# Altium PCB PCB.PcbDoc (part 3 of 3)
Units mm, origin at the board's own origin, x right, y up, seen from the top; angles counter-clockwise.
Board outline 43.18 x 22.86 mm, 6 copper layers (TOP, L2_GND, L3_SIG, L4_PWR, L5_GND, BOTTOM), stack 1.573 mm thick; 127 components, 116 nets, 532 pads, 386 vias.
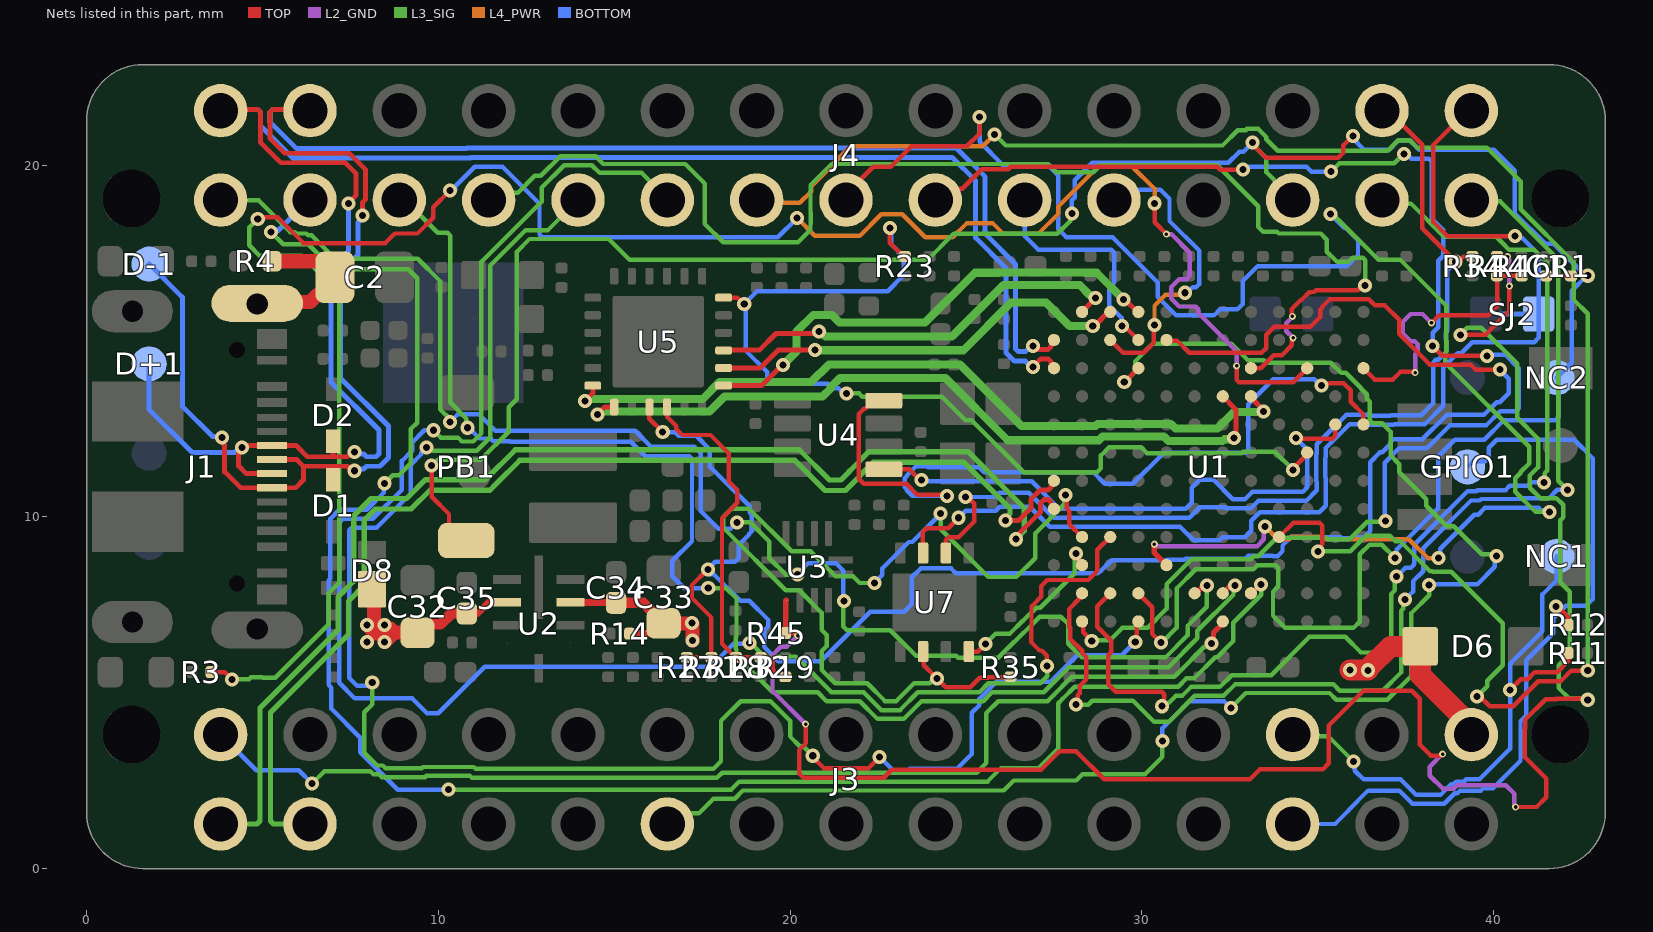
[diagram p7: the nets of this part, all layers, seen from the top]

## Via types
v1: diameter 0.4, hole 0.2, TOP to BOTTOM, tented both sides, 318 vias
v2: diameter 0.2, hole 0.1, TOP to L2_GND, tented both sides, 68 vias

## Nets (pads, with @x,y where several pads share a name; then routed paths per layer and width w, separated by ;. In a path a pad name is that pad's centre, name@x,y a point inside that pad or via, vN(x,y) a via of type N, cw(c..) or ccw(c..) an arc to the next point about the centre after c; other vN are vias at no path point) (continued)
NetR44_1: R44.1 R45.1 U3.1 | length 54.8
  TOP w0.127: v2(20.442,4.108) 20.442,3.56 20.255,3.373 20.255,2.71 20.382,2.582 22.664,2.582 22.895,2.813 27.134,2.813 27.66,3.34 28.13,3.34 28.93,2.54 33.075,2.54 33.356,2.821 35.145,2.821 35.318,2.994 35.318,4.07 36.303,5.056 37.673,5.056 37.9,4.828 37.9,3.531 38.215,3.215 38.508,3.215 v2(38.551,3.259) ; v1(39.056,15.178) 39.772,15.178 40.453,15.859 v2(40.453,16.565) ; R44.1@40.1,17.406 40.367,17.406 40.373,17.399 v2(40.403,17.399) ; v2(40.628,1.753) 41.223,1.753 41.5,2.031 41.5,2.562 40.894,3.168 40.894,3.969 40.905,3.98 40.905,4.243 41.482,4.82 41.768,4.82 41.774,4.826 42.656,4.826 v1(42.68,4.802)
  TOP w0.15: U3.1@19.889,7.63 19.875,7.616 R45.1@19.875,6.7 20.139,6.7 v2(20.214,6.625)
  L2_GND w0.127: v2(20.214,6.625) 19.899,6.31 19.737,6.31 19.5,6.073 19.5,5.05 v2(20.442,4.108) ; v2(38.551,3.259) 38.186,2.894 38.186,2.644 38.553,2.277 38.871,2.277 38.963,2.37 40.351,2.37 40.594,2.127 40.594,1.787 v2(40.628,1.753) ; v2(40.403,17.399) 40.403,17.379 40.45,17.332 40.45,16.568 v2(40.453,16.565)
  L3_SIG w0.127: v1(39.056,15.178) 39.257,15.379 39.655,15.379 40.673,14.362 40.673,12.82 41.268,12.225 41.268,11.415 41.032,11.179 41.032,10.834 41.334,10.533 41.79,10.533 41.979,10.343 41.979,9.985 41.899,9.905 41.899,8.142 42.172,7.869 42.172,6.106 41.849,5.783 41.849,5.139 42.159,4.828 42.654,4.828 v1(42.68,4.802)
NetU1_E11: U1.E11 U4.1 | length 16.4
  TOP w0.127: U4.1@22.765,11.356 23.388,11.356 23.691,11.053 v1(23.74,11.053) ; v1(34.379,12.246) 34.395,12.23 35.428,12.23 35.502,12.304 U1.E11@35.502,12.63
  BOTTOM w0.127: v1(23.74,11.053) 23.781,11.012 26.869,11.012 27.648,10.233 31.249,10.233 31.42,10.404 31.42,10.833 31.642,11.056 32.037,11.056 32.589,10.503 32.933,10.503 33.14,10.71 34.573,10.71 34.705,10.842 34.705,11.92 v1(34.379,12.246)
NetU1_E12: U1.E12 U4.4 | length 23.3
  TOP w0.127: U4.4@22.665,13.306 22.365,13.306 22.13,13.071 22.094,13.071 21.949,12.927 21.949,11.085 22.094,10.94 23.301,10.94 23.616,10.625 24.431,10.625 v1(24.462,10.594) ; v1(35.104,13.742) 35.155,13.794 35.35,13.794 35.351,13.796 35.745,13.796 35.937,13.603 35.937,13.279 36.302,12.913 U1.E12@36.302,12.63
  BOTTOM w0.127: v1@24.456,10.6 23.477,10.6 23.314,10.763 23.314,10.8 23.266,10.847 23.266,11.107 23.314,11.155 23.314,11.179 23.578,11.443 23.902,11.443 23.927,11.419 25.364,11.419 25.516,11.266 28.627,11.266 28.95,10.943 29.746,10.943 30.636,11.833 32.466,11.833 32.476,11.823 32.956,11.823 33.03,11.898 33.03,13.205 33.739,13.913 34.902,13.913 35.073,13.742 v1(35.104,13.742)
NetU1_K2: U1.K2 U7.4 | length 4.9
  TOP w0.127: U7.4@25.082,6.171 25.332,6.171 v1(25.553,6.391)
  TOP w0.15: v1(28.125,8.96) 28.173,8.913 28.173,8.814 28.302,8.684 U1.K2@28.302,8.63
  L3_SIG w0.127: v1(25.553,6.391) 25.845,6.684 26.25,6.684 26.613,7.047 26.623,7.047 26.996,7.42 27.115,7.42 28.091,8.396 28.091,8.927 v1(28.125,8.96)
PA20_TCC4_WO0_1: J4.16 U1.K5 | length 48
  TOP w0.127: J4.16@21.59,19.05 21.59,19.179 22.365,19.954 22.868,19.954 23.451,20.538 25.027,20.538 25.39,20.9 v1(25.39,21.37)
  TOP w0.15: v2(30.357,9.224) 30.357,8.975 U1.K5@30.702,8.63
  L2_GND w0.127: v2(30.357,9.224) 30.377,9.224 30.431,9.17 33.279,9.17 33.471,9.362 33.471,9.701 v1(33.502,9.733)
  L3_SIG w0.127: v1(35.368,18.608) 35.433,18.608 36.734,17.307 37.353,17.307 38.661,15.999 38.661,14.695 38.621,14.655 38.621,14.387 41.014,11.995 41.014,11.52 40.778,11.284 40.778,11.26 40.616,11.098 40.616,10.72 41.194,10.142 v1(41.589,10.142)
  L4_PWR w0.127: v1(33.502,9.733) 33.866,9.37 34.192,9.37 34.255,9.433 35.157,9.433 35.22,9.37 37.59,9.37 38.129,8.83 v1(38.432,8.83)
  BOTTOM w0.127: v1(25.39,21.37) 25.39,20.666 26.053,20.002 27.334,20.002 27.626,19.71 27.626,18.794 27.622,18.79 27.622,18.186 27.851,17.957 27.978,17.957 27.979,17.956 29.169,17.956 30.449,16.677 30.449,16.265 30.984,15.73 32.051,15.73 32.223,15.902 32.72,15.902 32.866,16.047 32.866,16.706 33.291,17.131 35.828,17.131 36.148,17.451 36.148,17.717 36.15,17.72 36.15,17.87 35.799,18.221 35.755,18.221 v1(35.368,18.608) ; v1(38.432,8.83) 38.485,8.883 38.485,9.094 39.456,10.065 39.563,10.065 39.754,10.256 40.656,10.256 ; 40.656,10.255 41.282,10.255 41.343,10.194 41.537,10.194 v1(41.589,10.142)
PA21_TCC4_WO1_1: J4.18 U1.M2 | length 41.3
  TOP w0.127: J4.18@24.13,19.05 24.205,19.125 24.622,19.125 24.829,19.332 24.899,19.332 25.451,19.884 26.2,19.884 26.276,19.961 32.144,19.961 32.228,19.876 v1(32.876,19.876) ; U1.M2@28.302,7.03 28.337,6.996 28.337,6.718 v1(28.577,6.477) ; v1(38.271,14.857) 38.545,14.583 39.455,14.583 39.459,14.579 v1(39.813,14.579)
  L3_SIG w0.127: v1(28.577,6.477) 28.59,6.49 29.085,6.49 29.449,6.854 30.169,6.854 30.705,7.39 30.705,8.086 31.414,8.795 33.099,8.795 33.183,8.879 33.309,8.879 33.839,9.409 34.231,9.409 34.236,9.415 35.23,9.415 35.277,9.367 35.913,9.367 36.41,9.864 36.908,9.864 v1(36.931,9.888) ; v1(35.378,19.819) 35.619,20.06 37.182,20.06 37.439,20.317 v1(37.456,20.317)
  BOTTOM w0.127: v1(32.876,19.876) 32.95,19.876 33.035,19.961 34.684,19.961 34.826,19.819 v1(35.378,19.819) ; v1(36.931,9.888) 36.908,9.912 36.908,11.545 37.316,11.953 38.08,11.953 38.095,11.969 38.122,11.969 38.767,12.614 39.799,12.614 40.194,13.009 40.64,13.009 40.717,13.086 40.717,14.227 40.326,14.618 39.852,14.618 v1(39.813,14.579) ; v1(37.456,20.317) 37.53,20.317 37.662,20.185 38.159,20.185 38.238,20.106 38.238,18.495 38.574,18.16 38.574,17.428 38.428,17.282 38.428,15.395 38.271,15.238 v1(38.271,14.857)
PA23_TCC5_WO1_1: J4.10 U1.M4 | length 48.9
  TOP w0.127: v1(20.645,3.211) 20.645,3.171 20.956,2.859 22.236,2.859 22.548,3.172 v1(22.548,3.175) ; v1(29.814,6.448) 29.86,6.493 29.86,6.987 U1.M4@29.902,7.03
  L3_SIG w0.127: v1(8.12,5.294) 8.12,4.67 7.896,4.445 7.896,3.297 8.259,2.934 8.422,2.934 8.496,2.859 9.525,2.859 9.556,2.891 11.005,2.891 11.061,2.835 17.816,2.835 18.036,3.055 18.036,4.202 18.594,4.761 19.444,4.761 20.001,4.204 20.001,3.759 20.276,3.484 20.372,3.484 v1(20.645,3.211) ; v1(9.667,11.976) 9.741,11.976 9.832,11.885 11.094,11.885 11.478,12.269 11.478,17.147 12.488,18.157 13.117,18.157 J4.10@13.97,19.01
  BOTTOM w0.127: v1(8.12,5.294) 8.028,5.202 7.688,5.202 7.46,5.429 7.46,9.62 7.535,9.694 8.243,9.694 9.218,10.669 9.218,11.487 9.507,11.777 9.507,11.823 9.661,11.976 v1(9.667,11.976) ; v1(22.548,3.175) 22.984,2.738 23.307,2.738 23.406,2.836 24.743,2.836 25.165,3.259 25.165,4.433 25.383,4.651 25.383,4.835 25.862,5.315 27.414,5.315 28.165,6.066 29.432,6.066 v1(29.814,6.448)
PB11_TCC3_WO6_1: J4.14 U1.J9 | length 53.3
  TOP w0.127: U1.J9@33.902,9.43 34.303,9.831 35.059,9.831 35.137,9.753 35.137,9.219 35.015,9.097 v1(35.015,9.023) ; v1(39.534,4.897) 39.608,4.897 39.89,4.615 40.558,4.615 41.271,5.328 41.557,5.328 41.563,5.334 41.917,5.334 41.962,5.378 41.962,5.38 42.19,5.609 42.192,5.609 42.215,5.631 v1(42.68,5.631)
  L3_SIG w0.127: v1(25.817,20.876) 26.132,20.561 32.295,20.561 32.731,20.997 32.952,20.997 32.986,21.032 33.309,21.032 33.538,20.803 33.538,20.741 33.869,20.41 36.997,20.41 37.295,20.707 37.618,20.707 37.823,20.503 39.805,20.503 40.426,19.882 40.43,19.882 40.774,19.538 40.774,18.749 42.275,17.248 42.275,16.184 42.68,15.78 v1(42.68,5.631) ; v1(35.015,9.023) 35.928,9.023 36.371,9.466 37.055,9.466 37.206,9.315 37.34,9.315 38.205,8.45 38.261,8.45 38.271,8.44 38.799,8.44 40.262,6.977 40.262,5.781 40.205,5.724 40.203,5.724 39.826,5.346 39.826,5.188 v1(39.534,4.897)
  L4_PWR w0.127: J4.14@19.05,19.05 19.169,18.931 20.276,18.931 20.598,19.253 20.598,19.405 21.729,20.536 25.476,20.536 v1(25.817,20.876)
PB16_GPIO_1: R3.2 U1.C10 | length 57.9
  TOP w0.127: R3.2@3.536,5.59 3.927,5.59 v1(4.134,5.384) ; v1(4.865,18.476) 4.906,18.517 5.435,18.517 6.164,17.788 8.488,17.788 8.76,18.06 9.405,18.06 9.852,18.506 9.852,18.802 v1(10.333,19.283) ; v1(30.365,18.918) 30.365,18.377 v2(30.7,18.042) ; v2@32.699,14.298 v2(32.699,14.294) 32.695,14.289 32.695,13.901 32.764,13.832 34.305,13.832 U1.C10@34.702,14.23
  L2_GND w0.127: v2(30.7,18.042) 30.717,18.042 30.719,18.043 30.837,18.043 31.366,17.515 31.366,16.852 31.278,16.765 31.066,16.765 30.837,16.536 30.837,16.213 31.066,15.984 31.529,15.984 31.603,15.909 31.603,15.799 32.699,14.703 v2(32.699,14.294)
  L3_SIG w0.127: v1(4.134,5.384) 4.616,5.384 4.67,5.437 4.994,5.437 5.001,5.431 5.364,5.431 6.882,6.948 6.882,7.837 7.178,8.134 7.178,16.372 6.121,17.429 4.912,17.429 4.62,17.722 4.62,18.231 v1(4.865,18.476)
  L4_PWR w0.127: v1(20.2,18.5) 20.702,17.998 21.985,17.998 22.594,18.607 23.189,18.607 23.845,17.951 24.623,17.951 25.018,18.346 25.769,18.346 26.055,18.06 27.064,18.06 27.621,18.616 27.621,18.653 27.623,18.655 27.623,18.828 28.797,20.002 29.689,20.002 30.365,19.326 v1(30.365,18.918)
  BOTTOM w0.127: v1(10.333,19.283) 10.479,19.283 10.479,19.404 11.036,19.961 11.824,19.961 12.875,18.909 12.875,18.025 12.95,17.951 19.651,17.951 v1(20.2,18.5)
PB24_TCC6_WO1_1: J4.8 U1.C8 | length 36.4
  TOP w0.127: U1.C8@33.102,14.23 33.386,14.23 33.751,14.596 33.985,14.596 34.268,14.879 34.268,15.008 34.286,15.026 34.286,15.077 v2(34.3,15.091) ; v2(34.283,15.701) 34.269,15.715 34.269,15.766 34.268,15.767 34.268,15.912 34.499,16.143 34.505,16.143 34.558,16.195 34.567,16.195 34.758,16.386 34.802,16.386 34.812,16.396 34.9,16.396 34.953,16.45 36.144,16.45 36.28,16.586 v1(36.35,16.586)
  L2_GND w0.127: v2(34.283,15.701) 34.283,15.685 34.11,15.513 34.11,15.28 v2(34.3,15.091)
  L3_SIG w0.127: J4.8@11.43,19.05 11.592,19.212 12.255,19.212 12.744,19.7 12.914,19.7 13.47,20.256 14.47,20.256 14.691,20.035 17.018,20.035 17.574,19.479 17.574,18.331 18.097,17.808 20.226,17.808 20.58,18.163 20.58,18.328 20.59,18.338 20.59,18.662 20.58,18.672 20.58,19.437 21.178,20.035 27.344,20.035 27.574,19.804 28.617,19.804 28.815,20.002 32.145,20.002 33.312,18.835 33.312,18.247 33.447,18.112 33.844,18.112 33.896,18.06 35.087,18.06 35.262,17.884 35.262,17.544 35.555,17.251 35.879,17.251 35.999,17.371 36.28,17.371 36.354,17.297 36.354,16.59 v1(36.35,16.586)
PC02_GPIO_1: R44.2 R46.1 U1.C12 | length 8.1
  TOP w0.127: U1.C12@36.302,14.23 36.626,13.906 37.137,13.906 37.353,14.123 37.752,14.123 v2(37.77,14.105) ; v2(38.237,15.515) 38.453,15.731 39.847,15.731 40.1,15.984 R44.2@40.1,16.856 R46.1@40.8,16.856
  L2_GND w0.127: v2(37.77,14.105) 37.77,14.633 37.84,14.703 37.84,14.915 37.765,14.99 37.649,14.99 37.421,15.218 37.421,15.542 37.649,15.771 37.982,15.771 v2(38.237,15.515)
PC19_TCC1_WO4_1: J4.22 U1.B3 | length 8.7
  TOP w0.127: U1.B3@29.102,15.03 29.468,14.664 30.054,14.664 30.337,14.948 30.337,15.437 v1(30.362,15.461)
  L4_PWR w0.127: v1(30.362,15.461) 30.362,16.006 30.673,16.318 31.036,16.318 31.04,16.322 31.175,16.322 v1(31.227,16.374)
  BOTTOM w0.127: J4.22@29.21,19.05 29.469,19.309 30.527,19.309 30.788,19.047 30.788,18.416 31.63,17.573 31.63,16.621 31.54,16.532 31.443,16.532 31.285,16.374 v1(31.227,16.374)
PC20_TCC1_WO5_1: J4.20 U1.B4 | length 6.7
  TOP w0.127: v1(29.432,15.432) 29.501,15.432 U1.B4@29.902,15.03
  BOTTOM w0.127: J4.20@26.67,19.05 26.67,17.986 27.054,17.602 29.128,17.602 29.213,17.516 29.213,16.674 29.076,16.537 29.076,16.015 29.432,15.659 v1(29.432,15.432)
PD11_TCC2_WO2_1: J4.12 U1.J3 | length 50.8
  TOP w0.127: v1(27.308,5.761) 27.303,5.766 27.303,6.054 27.154,6.203 27.091,6.203 26.862,6.431 26.862,6.495 26.862,6.755 26.864,6.757 26.864,7.455 27.137,7.727 27.137,8.031 27.314,8.208 28.481,8.208 28.737,8.464 28.737,9.065 U1.J3@29.102,9.43
  L3_SIG w0.127: v1(9.864,12.465) 10.072,12.257 10.558,12.257 10.67,12.146 10.996,12.146 11.224,12.374 11.224,17.252 12.94,18.968 12.94,19.367 13.575,20.002 14.365,20.002 14.586,19.781 15.779,19.781 J4.12@16.51,19.05 ; v1(18.846,6.417) 18.885,6.417 19.269,6.033 20.157,6.033 21.175,5.015 22.089,5.015 22.593,4.51 23.127,4.51 23.631,5.015 25.384,5.015 25.638,5.269 27.109,5.269 27.308,5.467 v1(27.308,5.761)
  BOTTOM w0.127: v1(9.864,12.465) 9.86,12.462 9.6,12.462 9.253,12.115 9.253,11.882 8.964,11.592 8.964,10.775 8.138,9.948 7.289,9.948 7.179,9.838 7.179,5.285 7.618,4.846 9.252,4.846 9.677,4.421 10,4.421 11.322,5.743 17.742,5.743 18.392,6.392 18.821,6.392 v1(18.846,6.417)
PHYAD_1:0: R27.1 R31.1 U1.B5 U5.15 | length 52.8
  TOP w0.127: U5.15@16,13.125 16,12.796 v1(16.379,12.417) ; R27.1@17.064,6.006 17.71,6.006 17.77,6.006 17.764,6.011 17.764,7.14 17.211,7.694 17.211,8.066 17.648,8.503 v1(17.665,8.503) ; U1.B5@30.702,15.03 30.716,15.016 30.999,15.016 31.351,14.664 33.403,14.664 33.537,14.798 33.537,15.181 33.766,15.41 34.799,15.41 35.068,15.679 35.068,15.885 35.137,15.954 35.137,15.981 35.351,16.196 36.454,16.196 36.527,16.122 36.636,16.013 36.907,16.013 37.317,15.603 37.317,15.204 38.193,14.329 39.35,14.329 39.49,14.188 v1@40.179,14.188
  BOTTOM w0.127: v1(16.379,12.417) 16.389,12.407 16.733,12.407 16.833,12.307 17.331,12.307 17.719,11.919 17.719,11.435 18.851,10.303 18.851,10.125 18.909,10.067 18.909,9.594 18.845,9.53 18.845,9.505 18.543,9.202 18.543,8.838 18.433,8.729 17.876,8.729 17.665,8.518 17.665,8.433 v1@17.718,8.38 ; v1@17.731,8.366 17.835,8.366 18.588,7.614 18.844,7.614 19.374,7.083 19.374,6.885 19.26,6.771 19.26,6.306 19.665,5.901 20.872,5.901 22.277,7.306 23.246,7.306 23.462,7.522 23.462,8.285 23.712,8.535 24.577,8.535 24.713,8.399 27.6,8.399 27.603,8.403 28.75,8.403 28.808,8.461 28.837,8.461 29.144,8.768 30.717,8.768 30.727,8.778 31.212,8.778 31.25,8.816 32.946,8.816 33.032,8.902 33.721,8.902 33.735,8.888 33.864,8.888 34.001,9.025 34.001,9.186 34.231,9.416 34.238,9.416 34.255,9.433 34.578,9.433 34.582,9.43 35.662,9.43 35.697,9.395 36.021,9.395 36.055,9.43 36.32,9.43 36.493,9.602 36.493,11.559 36.77,11.836 36.839,11.836 37.068,12.065 37.068,12.083 37.074,12.089 37.074,12.133 37.148,12.207 37.975,12.207 38.668,12.901 39.726,12.901 40.089,13.263 40.181,13.263 40.436,13.517 40.436,13.932 v1(40.18,14.188)
PHYAD_2: R19.1 R28.1 R32.1 U5.16 | length 10.6
  TOP w0.127: U5.16@16.5,13.125 16.5,12.848 16.769,12.579 16.769,12.491 16.93,12.33 17.735,12.33 18.25,11.815 18.25,11.017 18.5,10.767 18.5,10.402 18.236,10.138 18.064,9.967 18.064,9.297 ; 18.064,9.297 18.064,6.391 18.449,6.006 R32.1@19.164,6.006 19.384,6.006 19.504,5.886 19.504,5.663 19.57,5.597 19.57,5.53 19.644,5.456 R19.1@19.865,5.456
R\E\S\E\T\_1: C1.2 J4.26 NC2.X PB1.2 R1.1 U1.L4 | length 75.2
  TOP w0.127: v1(9.809,11.462) 9.809,10.576 10.302,10.083 10.302,9.753 10.461,9.594 10.53,9.594 PB1.2@10.794,9.33 ; U1.L4@29.902,7.83 30.296,7.436 30.296,6.673 v1(30.542,6.427) ; v1(33.148,20.641) 33.148,20.597 33.53,20.215 34.789,20.215 34.794,20.209 35.582,20.209 35.733,20.36 35.733,20.568 v1(36.001,20.837) ; C1.2@41.5,16.856 R1.1@42.2,16.856 42.202,16.857 42.678,16.857 v1(42.68,16.859)
  L3_SIG w0.127: v1(9.809,11.462) 9.978,11.631 11.208,11.631 12,12.423 12,13.118 12.225,13.343 12.225,17.534 12.593,17.903 14.843,17.903 15.438,17.307 23.907,17.307 24.648,18.049 27.6,18.049 27.961,18.41 27.961,18.576 v1(28.013,18.628) ; v1(30.542,6.427) 30.568,6.427 30.988,6.847 30.988,7.967 31.532,8.511 33.174,8.511 33.288,8.625 33.809,8.625 33.883,8.55 33.883,8.027 33.73,7.875 33.73,7.19 34.076,6.844 36.018,6.844 36.198,7.024 36.198,7.898 36.2,7.9 36.2,8.936 36.476,9.212 36.826,9.212 v1(37.204,8.834) ; v1(33.148,20.641) 33.148,20.597 33.543,20.201 33.543,19.797 J4.26@34.29,19.05
  BOTTOM w0.127: v1(28.013,18.628) 28.013,19.005 28.09,19.082 28.09,19.57 28.588,20.069 31.175,20.069 31.178,20.066 31.388,20.066 31.391,20.069 32.458,20.069 32.768,20.378 32.885,20.378 v1(33.148,20.641) ; v1(36.001,20.837) 36.001,20.763 36.32,20.445 37.032,20.445 37.295,20.707 37.618,20.707 37.885,20.44 40.009,20.44 40.609,19.84 40.609,18.629 41.473,17.765 41.716,17.765 42.622,16.859 v1(42.68,16.859) ; v1(37.204,8.834) 37.255,8.885 37.255,9.082 38.427,10.254 38.427,11.723 38.897,12.192 39.736,12.192 40.299,12.755 41.76,12.755 41.838,12.832 41.838,13.926 NC2.X@41.803,13.961 42.226,14.384 42.226,16.43 42.644,16.848 v1@42.68,16.848
"RS485 A_1": J4.27 R34.2 U7.6 | length 28.2
  TOP w0.127: U7.6@24.432,8.971 24.42,8.983 24.42,9.334 24.514,9.428 24.798,9.428 25.24,9.87 25.24,10.372 25.044,10.567 v1(24.988,10.567) ; J4.27@36.83,21.55 37.009,21.55 37.974,20.585 37.974,18.207 v1(38.924,17.256) 38.998,17.256 39.145,17.403 R34.2@39.399,17.403
  BOTTOM w0.127: v1(24.988,10.567) 25.83,10.567 25.951,10.688 26.789,10.688 27.498,9.979 31.354,9.979 31.65,10.275 32.366,10.275 32.391,10.249 33.107,10.249 33.314,10.456 34.678,10.456 34.977,10.755 34.977,11.006 34.959,11.024 34.959,11.779 34.977,11.797 34.977,12.066 35.818,12.907 36.495,12.907 36.53,12.871 37.064,12.871 37.088,12.896 37.944,12.896 38.281,13.232 38.281,14.386 38.362,14.466 38.433,14.466 38.661,14.695 38.661,15.019 38.642,15.037 38.642,15.25 38.682,15.29 38.682,17.014 v1(38.924,17.256)
"RS485 B_1": J4.29 SJ2.1 U7.7 | length 32.4
  TOP w0.127: U7.7@23.774,8.978 23.774,9.573 23.884,9.682 24.5,9.682 v1(24.795,9.977) ; J4.29@39.37,21.55 39.263,21.55 38.293,20.58 38.293,18.386 38.703,17.976 40.6,17.976 v1(40.607,17.983)
  BOTTOM w0.127: v1(24.795,9.977) 24.994,10.177 25.85,10.177 25.962,10.289 26.816,10.289 27.38,9.725 31.087,9.725 31.475,9.337 32.209,9.337 32.295,9.423 32.924,9.423 33.112,9.611 33.112,9.895 33.351,10.134 35.047,10.134 35.231,10.318 35.231,11.111 35.213,11.129 35.213,11.674 35.231,11.691 35.231,11.96 35.912,12.642 36.4,12.642 36.425,12.617 37.169,12.617 37.194,12.642 38.05,12.642 38.573,13.165 38.573,14.247 38.977,14.652 39.082,14.652 39.4,14.969 41.159,14.969 41.29,15.101 41.29,15.762 SJ2.1@41.283,15.769 41.283,17.462 40.799,17.946 40.644,17.946 v1(40.607,17.983)
RST#: R23.1 U1.F10 U5.24 | length 28
  TOP w0.127: U5.24@18.11,16.235 18.504,16.235 18.684,16.055 v1(18.697,16.055) ; v1(22.837,18.216) 22.837,17.799 23.109,17.527 23.119,17.527 23.24,17.406 R23.1@23.265,17.406 ; v1(34.302,11.333) 34.302,11.382 34.702,11.782 U1.F10@34.702,11.83
  L3_SIG w0.127: v1(21.598,13.512) 21.962,13.512 22.052,13.421 24.318,13.421 24.995,12.745 25.168,12.745 26.64,11.273 28.725,11.273 28.839,11.387 28.839,11.581 28.839,11.749 29.068,11.978 29.248,11.978 29.988,11.978 30.148,11.818 32.84,11.818 32.878,11.855 33.78,11.855 v1(34.302,11.333)
  BOTTOM w0.127: v1(21.598,13.512) 21.529,13.512 21.377,13.663 21.356,13.663 21.198,13.663 21.068,13.794 19.435,13.794 19.348,13.881 19.348,14.121 18.734,14.735 18.734,16.018 v1(18.697,16.055) 19.062,16.42 22.779,16.42 23.227,16.868 23.227,17.359 23.09,17.496 23.09,17.545 22.88,17.755 22.88,18.173 v1(22.837,18.216)
RXD0: U1.D7 U5.13 | length 21.4
  TOP w0.142: v1(14.523,12.908) 14.523,12.917 14.735,13.129 14.956,13.129 14.96,13.125 U5.13@15,13.125 ; U1.D7@32.302,13.43 32.676,13.057 32.676,12.475 32.674,12.474 32.674,12.291 v1(32.625,12.242)
  L3_SIG w0.231: v1(14.523,12.908) 14.569,12.908 14.657,12.996 17.706,12.996 18.135,13.425 20.925,13.425 21.156,13.656 21.156,13.695 21.416,13.956 24.414,13.956 26.19,12.18 28.78,12.18 28.884,12.284 30.628,12.284 30.754,12.157 32.296,12.157 32.348,12.21 32.592,12.21 v1(32.625,12.242)
RXD1: U1.D8 U5.12 | length 21.8
  TOP w0.142: v1(14.163,13.293) 14.39,13.52 U5.12@14.39,13.735 ; U1.D8@33.102,13.43 33.102,13.394 33.457,13.04 v1(33.457,13.004)
  L3_SIG w0.231: v1(14.163,13.293) 14.186,13.293 14.218,13.326 14.315,13.326 14.343,13.354 17.516,13.354 17.995,13.833 20.599,13.833 21.106,14.34 24.832,14.34 26.584,12.588 28.681,12.588 28.736,12.642 30.836,12.642 30.962,12.515 32.148,12.515 32.62,12.988 33.441,12.988 v1(33.457,13.004)
SPI2_CS: J3.12 U1.C4 | length 44.2
  TOP w0.127: v1(29.501,13.832) 29.503,13.832 U1.C4@29.902,14.23 U1.C4@29.902,14.23
  L3_SIG w0.127: J3.12@16.51,1.27 16.811,1.571 17.4,1.571 17.822,1.992 18.428,1.992 18.658,2.223 26.077,2.223 26.362,2.507 28.14,2.507 28.314,2.681 30.091,2.681 30.588,3.178 v1(30.588,3.634) ; v1(29.501,13.832) 29.526,13.832 29.819,14.125 29.819,14.434 30.315,14.93 32.541,14.93 33.018,14.452 33.468,14.452 33.534,14.387 35.376,14.387 35.665,14.098 35.801,14.098 36.225,13.674 36.225,13.661 36.399,13.487 36.399,13.364 36.482,13.282 36.482,12.744 36.564,12.661 36.833,12.661 37.074,12.42 37.074,11.751 37.323,11.503 37.323,11.272 38.092,10.503 38.092,10.315 38.667,9.739 38.866,9.739 39.665,8.941 40.038,8.941 v1(40.09,8.888) ; v1(32.533,4.567) 32.96,4.994 35.337,4.994 35.526,4.805 36.983,4.805 37.666,5.488 37.666,7.269 38.169,7.773 v1(38.169,8.06)
  BOTTOM w0.127: v1(30.588,3.634) 30.588,3.995 31.355,4.763 32.337,4.763 v1(32.533,4.567) ; v1(38.169,8.06) 38.191,8.081 39.538,8.081 40.038,8.581 40.038,8.836 v1(40.09,8.888)
SPI5_CS_1: J4.6 U1.L7 | length 38.8
  TOP w0.15: U1.L7@32.302,7.83 32.473,8 32.602,8 v1(32.65,8.048)
  L3_SIG w0.127: J4.6@8.89,19.05 9.01,19.05 9.98,18.081 10.075,18.081 10.08,18.076 10.263,18.076 10.337,18.002 10.337,13.259 10.797,12.8 10.797,12.573 v1(10.834,12.536) ; v1(17.673,7.976) 18.185,7.976 18.476,7.684 18.476,6.6 18.455,6.579 18.455,6.255 18.476,6.234 18.476,6.041 19.503,5.015 20.783,5.015 21.037,4.761 21.984,4.761 22.488,4.256 23.232,4.256 23.736,4.761 25.489,4.761 25.743,5.015 27.215,5.015 27.93,5.729 30.759,5.729 31.578,6.548 31.578,6.763 32.608,7.792 32.608,8.006 v1(32.65,8.048)
  BOTTOM w0.127: v1(10.834,12.536) 10.865,12.536 11.17,12.23 11.485,12.23 11.559,12.156 12.023,12.156 12.04,12.139 15.469,12.139 15.882,11.726 17.137,11.726 17.211,11.652 17.211,9.312 16.652,8.753 16.652,8.316 16.991,7.976 v1(17.673,7.976)
SPI5_MISO_1: J4.2 U1.L6 | length 41.6
  TOP w0.15: U1.L6@31.502,7.83 31.537,7.83 31.708,8 31.802,8 v1(31.85,8.048)
  L3_SIG w0.127: J4.2@3.81,19.05 3.856,19.004 4.889,19.004 5.795,18.097 5.918,18.097 5.956,18.06 6.247,18.06 6.303,18.004 6.403,18.004 7.063,17.344 9.414,17.344 10.049,16.709 10.049,13.06 10.334,12.774 v1(10.334,12.703) ; v1(18.496,9.847) 18.864,9.847 19.409,9.301 19.409,8.829 19.876,8.363 v1(20.216,8.363) ; v1@21.527,7.664 21.516,7.653 21.516,6.885 21.62,6.781 22.85,6.781 23.582,6.05 24.724,6.05 24.773,6.001 25.915,6.001 26.153,6.239 26.164,6.239 26.628,6.702 26.638,6.702 27.102,7.166 27.697,7.166 27.908,6.954 27.908,6.397 28.299,6.006 30.674,6.006 31.301,6.634 31.301,6.902 31.85,7.451 v1(31.85,8.048)
  BOTTOM w0.127: v1(10.334,12.703) 10.558,12.927 11.148,12.927 11.622,12.452 15.594,12.452 16.048,11.998 17.281,11.998 17.465,11.814 17.465,10.16 17.963,9.663 18.308,9.663 18.493,9.847 v1(18.496,9.847) ; v1(20.216,8.363) 20.216,8.388 20.517,8.69 21.299,8.69 21.513,8.477 21.513,7.632 v1(21.537,7.608)
SPI5_MOSI_1: J4.4 U1.L8 | length 51.8
  TOP w0.15: U1.L8@33.102,7.83 33.125,7.83 33.372,8.076 v1(33.395,8.076)
  L3_SIG w0.127: v1(5.237,18.103) 5.591,17.75 6.298,17.75 7.007,17.04 9.144,17.04 9.398,16.785 9.398,12.681 9.218,12.501 9.218,11.526 8.881,11.19 8.704,11.19 v1(8.471,10.958) ; v1(10.293,2.246) 18.323,2.246 18.553,2.477 25.614,2.477 25.997,2.859 27.064,2.859 27.621,3.416 27.621,4.7 27.745,4.824 27.745,4.826 28.094,5.175 31.035,5.175 31.27,5.411 31.285,5.411 31.295,5.42 31.498,5.42 32.09,6.012 32.142,6.012 32.6,6.471 32.6,6.996 33.395,7.79 v1(33.395,8.076)
  BOTTOM w0.127: v1(8.471,10.958) 8.452,10.938 8.452,10.694 7.961,10.202 7.183,10.202 6.925,9.944 6.925,8.242 6.882,8.199 6.882,5.223 6.96,5.144 6.96,4.547 7.783,3.724 7.783,3.307 8.844,2.246 v1(10.293,2.246)
  BOTTOM w0.15: v1(5.237,18.103) 5.285,18.151 5.451,18.151 J4.4@6.35,19.05
SPI5_SCK_1: J3.1 U1.M7 | length 32.2
  TOP w0.15: v1(31.98,6.403) 31.98,6.471 32.039,6.53 32.039,6.712 32.302,6.976 U1.M7@32.302,7.03
  L3_SIG w0.127: v1(6.407,2.419) 6.76,2.772 8.061,2.772 8.154,2.68 8.317,2.68 8.391,2.605 9.63,2.605 9.661,2.637 10.9,2.637 10.955,2.581 17.921,2.581 18.071,2.731 25.305,2.731 25.58,3.006 25.58,4.423 25.917,4.761 27.322,4.761 27.491,4.929 27.491,4.931 27.97,5.41 27.972,5.41 28.014,5.452 30.919,5.452 31.026,5.559 31.027,5.559 31.776,6.308 31.811,6.308 31.906,6.403 v1(31.98,6.403)
  BOTTOM w0.127: J3.1@3.81,3.81 4.825,2.795 6.03,2.795 v1(6.407,2.419)
SWCLK_1: GPIO1.X J3.26 R12.1 | length 22.4
  TOP w0.127: v1(41.782,7.449) 41.83,7.449 42.117,7.162 42.117,6.931 R12.1@42.119,6.928
  BOTTOM w0.127: J3.26@34.29,1.27 35.496,1.27 35.877,1.651 35.877,1.665 36.433,2.221 37.317,2.221 37.694,1.843 38.598,1.843 38.901,2.145 38.972,2.145 39.047,2.221 39.643,2.221 39.713,2.291 39.991,2.291 40.767,3.067 40.767,4.192 40.927,4.352 40.927,5.926 41.696,6.694 41.696,7.113 v1@41.968,7.385 ; GPIO1.X@39.263,11.421 39.43,11.588 39.767,11.588 39.867,11.688 39.867,11.964 40.096,12.192 42.298,12.192 42.817,11.674 42.817,7.664 42.625,7.472 42.055,7.472 ; v1(41.782,7.449) 41.834,7.397 41.956,7.397 v1@41.968,7.385 ; 42.032,7.449 v1@41.968,7.385
SWDIO_1: J3.25 NC1.X R11.1 | length 15.8
  TOP w0.127: v1(40.47,5.079) 40.472,5.079 40.778,5.386 40.97,5.386 41.166,5.582 41.452,5.582 41.458,5.588 41.81,5.588 42.119,5.897 R11.1@42.119,6.128
  L3_SIG w0.127: J3.25@34.29,3.81 34.33,3.77 35.295,3.77 v1(36.017,3.049)
  BOTTOM w0.127: v1(36.017,3.049) 36.059,3.006 36.059,2.785 36.304,2.54 37.356,2.54 37.8,2.097 38.493,2.097 38.796,2.399 38.867,2.399 38.942,2.475 39.156,2.475 39.221,2.54 39.603,2.54 40.471,3.408 v1@40.471,5.079 ; v1@40.504,5.111 40.471,5.144 40.471,5.829 41.391,6.749 41.391,7.796 41.803,8.208 NC1.X@41.803,8.881
TXD0: U1.A3 U5.20 | length 12.2
  TOP w0.142: U5.20@18.11,14.235 19.149,14.235 19.663,14.749 20.712,14.749 v1(20.713,14.751) ; v1(28.606,15.43) 28.654,15.43 29.054,15.83 U1.A3@29.102,15.83
  L3_SIG w0.231: v1(20.713,14.751) 20.725,14.739 24.93,14.739 26.284,16.093 27.277,16.093 27.94,15.43 v1(28.606,15.43)
TXDI: U1.A2 U5.21 | length 12.2
  TOP w0.142: U5.21@18.117,14.742 19.125,14.742 19.601,15.219 20.607,15.219 20.61,15.221 20.77,15.221 v1(20.819,15.27) ; U1.A2@28.302,15.83 28.302,15.838 28.686,16.221 v1(28.686,16.228)
  L3_SIG w0.231: v1(20.819,15.27) 20.865,15.27 21.004,15.132 24.605,15.132 26.066,16.593 28.235,16.593 28.515,16.313 28.562,16.313 28.646,16.228 v1(28.686,16.228)
TXEN: U1.A4 U5.19 | length 14.1
  TOP w0.142: U5.19@18.11,13.735 19.197,13.735 19.78,14.319 v1(19.802,14.319) ; v1(29.485,16.18) 29.519,16.18 29.869,15.83 U1.A4@29.902,15.83
  L3_SIG w0.231: v1(19.802,14.319) 20.188,14.704 20.188,15.275 20.659,15.746 21.194,15.746 21.409,15.531 23.84,15.531 25.254,16.945 25.912,16.945 25.918,16.951 28.383,16.951 28.389,16.945 28.721,16.945 v1(29.485,16.18)
UART0_CTS: R35.1 U1.J2 U7.2 | length 28.5
  TOP w0.127: U7.2@23.782,6.171 23.799,6.154 23.799,5.786 24.164,5.42 v1@24.164,5.39 ; v1(24.18,5.405) 24.425,5.16 25.127,5.16 25.393,5.426 25.636,5.426 25.648,5.439 26.163,5.439 26.169,5.444 R35.1@26.169,5.456 ; v1(27.828,10.623) 27.868,10.584 27.868,10.238 27.937,10.169 27.937,9.796 U1.J2@28.302,9.43
  L3_SIG w0.127: v1(22.395,8.123) 21.98,8.123 21.794,8.309 21.298,8.309 20.583,9.023 20.047,9.023 18.833,10.238 18.335,10.238 18.106,10.009 18.106,9.685 19.875,7.916 20.26,7.916 20.896,7.28 20.896,6.791 21.038,6.649 21.038,6.326 20.896,6.184 20.896,5.66 21.287,5.269 22.194,5.269 22.698,4.764 23.022,4.764 23.526,5.269 23.969,5.269 24.106,5.405 v1(24.18,5.405) ; v1(24.281,10.094) 24.281,9.65 25.638,8.293 26.433,8.293 26.97,8.83 26.97,9.531 27.798,10.36 27.798,10.593 v1(27.828,10.623)
  BOTTOM w0.127: v1(22.395,8.123) 22.624,8.352 22.624,8.535 23.377,9.288 23.475,9.288 v1(24.281,10.094)
UART6_RX_1: J4.28 U1.L3 | length 31.9
  TOP w0.127: U1.L3@29.102,7.83 28.737,7.464 28.737,6.879 29.132,6.484 29.132,6.153 29.05,6.071 29.05,5.24 29.258,5.032 30.564,5.032 30.638,4.958 30.638,4.83 30.626,4.817 30.626,4.671 v1(30.574,4.619)
  L3_SIG w0.127: v1(30.574,4.619) 30.648,4.619 30.748,4.719 30.772,4.719 30.963,4.91 31.144,4.91 31.4,5.166 32.22,5.166 32.556,5.502 33.68,5.502 34.768,6.59 35.787,6.59 36.232,6.146 36.751,6.146 37.089,6.483 37.089,7.809 37.192,7.912 37.192,8.256 v1(37.244,8.308) ; J4.28@36.83,19.05 36.969,18.911 37.654,18.911 38.602,17.963 40.075,17.963 40.217,17.821 40.445,17.592 41.165,17.592 41.522,17.235 41.522,11.309 41.46,11.248 41.46,11.011 v1(41.434,10.985)
  BOTTOM w0.127: v1(37.244,8.308) 37.487,8.551 37.643,8.551 37.745,8.652 37.745,9.212 39.263,10.731 39.51,10.731 39.544,10.764 40.343,10.764 40.464,10.885 40.98,10.885 41.079,10.985 v1(41.434,10.985)
UART6_TX_1: J4.30 U1.L2 | length 32.3
  TOP w0.127: v1(28.135,4.664) 28.177,4.706 28.177,4.928 28.23,4.98 28.23,5.189 28.425,5.384 28.425,6.015 28.31,6.13 28.31,6.192 27.97,6.532 27.97,6.845 27.937,6.879 27.937,7.383 28.212,7.658 28.212,7.679 28.302,7.77 U1.L2@28.302,7.83
  L3_SIG w0.127: v1(28.135,4.664) 28.48,4.664 28.589,4.773 29.749,4.773 30.352,4.171 30.764,4.171 31.505,4.912 32.325,4.912 32.662,5.248 35.442,5.248 35.631,5.059 36.852,5.059 37.371,5.578 37.371,7.333 37.427,7.39 37.427,7.595 v1(37.48,7.647) ; J4.30@39.41,19.01 39.45,18.97 40.194,18.97 41.841,17.323 41.841,11.034 v1(42.105,10.77)
  BOTTOM w0.127: v1(37.48,7.647) 37.712,7.879 37.712,8.17 37.999,8.457 37.999,9.107 39.36,10.468 39.606,10.468 39.649,10.51 40.761,10.51 40.784,10.533 41.575,10.533 41.813,10.77 v1(42.105,10.77)
USB_D_1_N: D1.2 D-1.X J1.A7 J1.B7 J4.3 U1.B1 | length 57
  TOP w0.14: v1(3.843,12.254) 3.893,12.204 3.893,12.072 3.923,12.042 3.923,11.284 4.377,10.83 J1.A7@5.276,10.83 5.943,10.83 6.163,11.05 6.163,11.443 ; J1.B7@5.306,11.66 J1.B7@5.276,11.63 5.976,11.63 6.163,11.443 ; J4.3@6.35,21.59 5.297,21.59 5.215,21.508 5.215,20.755 5.63,20.34 7.464,20.34 7.931,19.873 7.931,19.032 7.838,18.938 v1@7.838,18.57 ; D1.2@7.008,10.973 7.008,11.413 ; v1(7.616,11.314) 7.546,11.314 7.417,11.443 6.163,11.443 ; v1(26.902,14.861) 26.973,14.861 27.069,14.765 27.339,14.765 27.421,14.847 27.421,14.892 27.502,14.973 U1.B1@27.502,15.03
  BOTTOM w0.14: D-1.X@1.778,17.191 2.721,16.248 2.721,13.149 3.58,12.291 3.806,12.291 v1(3.843,12.254) ; J4.3@6.35,21.59 5.297,21.59 5.215,21.508 5.215,21.226 5.963,20.478 10.803,20.478 10.817,20.491 24.724,20.491 25.545,19.67 25.545,18.048 26.41,17.183 26.41,14.78 26.492,14.698 26.69,14.698 26.853,14.861 v1(26.902,14.861) ; v1(7.616,11.314) 7.666,11.364 7.879,11.364 7.958,11.443 8.34,11.443 8.581,11.683 8.581,12.585 7.219,13.946 7.219,16.959 7.717,17.457 7.717,18.379 7.837,18.5 v1(7.837,18.57)
USB_D_1_P: D2.2 D+1.X J1.A6 J1.B6 J4.1 U1.C1 | length 54.3
  TOP w0.14: J4.1@3.81,21.59 4.863,21.59 4.945,21.508 4.945,20.644 5.519,20.07 7.353,20.07 7.661,19.762 7.661,19.143 7.441,18.923 v1(7.441,18.917) ; J1.B6@5.276,11.23 4.543,11.23 4.323,11.449 4.323,11.808 4.475,11.96 4.475,12.03 J1.A6@5.276,12.03 5.957,12.03 6.275,11.713 7.013,11.713 ; D2.2@7.008,12.232 7.008,11.718 7.013,11.713 ; v1(7.616,11.841) 7.546,11.841 7.417,11.713 7.013,11.713 ; v1(26.902,14.265) 27.132,14.495 27.339,14.495 27.421,14.413 27.421,14.368 27.502,14.287 U1.C1@27.502,14.23
  BOTTOM w0.14: D+1.X@1.778,14.351 1.778,13.052 2.995,11.835 4.21,11.835 4.346,11.971 v1(4.417,11.971) ; J4.1@3.81,21.59 4.863,21.59 4.945,21.508 4.945,21.114 5.851,20.208 10.915,20.208 10.928,20.221 24.612,20.221 25.275,19.558 25.275,17.937 26.14,17.071 26.14,14.669 26.381,14.428 26.69,14.428 26.853,14.265 v1(26.902,14.265) ; v1@7.44,18.917 7.44,18.33 7.447,18.323 7.447,17.568 6.949,17.071 6.949,13.835 8.311,12.473 8.311,11.795 8.229,11.713 7.958,11.713 7.879,11.791 7.666,11.791 v1(7.616,11.841)
USB_SHIELD_1: C2.2 J1.SHIELD1 R4.2 | length 4.7
  TOP w0.4: J1.SHIELD1@4.851,16.05 4.906,16.106 6.351,16.106 6.554,16.309 6.707,16.309 7.058,16.66 C2.2@7.058,16.813 7.058,16.919 6.707,17.27 R4.2@5.271,17.27
USBFS_D_N: J3.4 U1.G1 | length 33.6
  TOP w0.14: v1(26.124,9.899) 26.502,9.899 26.847,10.244 26.847,10.501 27.111,10.765 27.339,10.765 27.421,10.847 27.421,10.892 27.502,10.973 U1.G1@27.502,11.03
  L3_SIG w0.15: J3.4@6.35,1.27 5.317,1.27 5.229,1.358 5.229,4.445 7.447,6.662 7.447,7.603 7.891,8.047 7.891,9.904 8.213,10.226 9.225,10.226 9.76,10.76 11.465,10.76 11.64,10.936 12.314,11.609 20.135,11.609 20.992,10.752 21.574,10.752 21.985,11.163 21.985,11.175 22.367,11.558 24.93,11.558 26.251,10.236 26.251,10.094 26.124,9.966 v1(26.124,9.899)
USBFS_D_P: J3.2 U1.H1 | length 35
  TOP w0.14: v1(26.421,9.367) 26.421,9.436 27.117,10.132 27.117,10.389 27.223,10.495 27.339,10.495 27.421,10.413 27.421,10.368 27.502,10.287 U1.H1@27.502,10.23
  L3_SIG w0.15: J3.2@3.81,1.27 4.842,1.27 4.93,1.358 4.93,4.569 7.147,6.786 7.147,7.727 7.591,8.171 7.591,10.028 8.089,10.526 9.101,10.526 9.636,11.06 11.34,11.06 12.189,11.909 20.259,11.909 21.116,11.052 21.449,11.052 21.685,11.288 21.685,11.299 22.243,11.857 25.054,11.857 26.658,10.252 26.658,9.604 v1(26.421,9.367)
VIN: C32.2 C33.2 C34.2 C35.2 D6.2 D8.C J3.29 R14.1 U2.2 U2.10 | length 17
  TOP w0.2: C35.2@10.809,7.256 11.11,7.256 11.426,7.572 U2.2@11.952,7.572 ; U2.10@13.752,7.572 15.039,7.572 C34.2@15.053,7.558 ; R14.1@15.438,6.682 16.001,6.682 16.291,6.972 16.396,6.972 C33.2@16.407,6.972
  TOP w0.3: C32.2@9.417,6.713 9.649,6.944 10.06,6.944 10.372,7.256 C35.2@10.809,7.256 ; C34.2@15.053,7.558 15.821,7.558 16.116,7.263 16.116,7.252 C33.2@16.396,6.972
  TOP w0.4: v1(7.973,6.923) 8.211,6.686 8.218,6.686 ; v1@8.108,6.796 8.167,6.854 8.167,7.886 D8.C@8.108,7.944 ; C32.2@9.417,6.713 8.757,6.713 ; C33.2@16.407,6.972 17.199,6.972 v1(17.206,6.979) 17.224,6.961 v1(17.224,6.493) ; 8.757,6.713 8.636,6.834 8.563,6.834 v1(8.473,6.923) v1(8.473,6.441) 8.486,6.441 8.757,6.713
  TOP w0.6: v1(35.924,5.648) v1@36.434,5.648 ; v1@36.434,5.69 37.066,6.322 D6.2@37.917,6.322 37.917,5.505 39.353,4.069 J3.29@39.353,3.787
  other v1: 36.434,5.641 7.973,6.441
pads on no net: Fiducial_1.1 Fiducial_2.1 J1.A8 J1.B8 J1.FIXING J1.SHIELD2 J1.SHIELD3 J1.SHIELD4 J2.FIX J4.21 U1.A5 U1.A7 U1.A9 U1.A10 U1.A11 U1.B7 U1.B9 U1.B10 U1.C2 U1.C11 U1.D3 U1.D10 U1.D12 U1.F3 U1.F11 U1.F12 U1.G2 U1.G3 U1.G10 U1.G11 U1.G12 U1.H2 U1.H8 U1.H9 U1.H10 U1.H11 U1.J1 U1.J5 U1.J6 U1.J11 U1.J12 U1.K6 U1.K7 U1.K8 U1.K10 U1.L5 U1.L9 U1.L10 U1.M3 U1.M5 U1.M6 U1.M11 U2.8 U3.12 U5.7 Y1.2 Y1.4

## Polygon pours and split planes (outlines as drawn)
GND on TOP "GND_L01_P011" (solid, remove dead copper, pour order 11): 1.6,0 cw(c1.6,1.6) 0,1.6 0,21.26 cw(c1.6,21.26) 1.6,22.86 41.58,22.86 cw(c41.58,21.26) 43.18,21.26 43.18,1.6 cw(c41.58,1.6) 41.58,0
GND on TOP "GND_L01_P007" (solid, remove dead copper, pour order 7): 16.472,9.778 16.637,9.778 17.753,9.778 17.848,9.682 17.848,8.389 17.656,8.197 16.472,8.197 16.39,8.279 16.39,9.577
+VBUS on TOP "VBUS" (solid, remove dead copper, pour order 8): 5.953,8.636 2.814,8.63 2.814,13.613 3.197,13.996 5.953,13.995
+3V3 on L4_PWR "+3V3_L04_P003" (solid, remove dead copper, pour order 3): 1.6,0 cw(c1.6,1.6) 0,1.6 0,21.26 cw(c1.6,21.26) 1.6,22.86 41.58,22.86 cw(c41.58,21.26) 43.18,21.26 43.18,1.6 cw(c41.58,1.6) 41.58,0
VIN on L4_PWR "VIN_L04_P001" (solid, remove dead copper, pour order 1): 8.942,5.783 8.771,5.925 7.652,5.925 7.604,5.987 7.604,7.132 7.653,7.181 8.771,7.181 8.84,7.112 16.57,7.112 16.927,7.468 18.002,7.468 18.727,6.743 36.077,6.743 37.014,5.805 37.014,5.028 36.879,4.892 9.148,4.892 8.942,5.16
GND on L2_GND "GND_L02_P005" (solid, remove dead copper, pour order 5): 1.6,0 cw(c1.6,1.6) 0,1.6 0,21.26 cw(c1.6,21.26) 1.6,22.86 41.58,22.86 cw(c41.58,21.26) 43.18,21.26 43.18,1.6 cw(c41.58,1.6) 41.58,0
GND on L5_GND "GND_L05_P006" (solid, remove dead copper, pour order 6): 1.6,0 cw(c1.6,1.6) 0,1.6 0,21.26 cw(c1.6,21.26) 1.6,22.86 41.58,22.86 cw(c41.58,21.26) 43.18,21.26 43.18,1.6 cw(c41.58,1.6) 41.58,0
GND on L3_SIG "GND_L03_P009" (solid, remove dead copper, pour order 9): 1.6,0 cw(c1.6,1.6) 0,1.6 0,21.26 cw(c1.6,21.26) 1.6,22.86 41.58,22.86 cw(c41.58,21.26) 43.18,21.26 43.18,1.6 cw(c41.58,1.6) 41.58,0
GND on BOTTOM "GND_L06_P010" (solid, remove dead copper, pour order 10): 1.6,0 cw(c1.6,1.6) 0,1.6 0,21.26 cw(c1.6,21.26) 1.6,22.86 41.58,22.86 cw(c41.58,21.26) 43.18,21.26 43.18,1.6 cw(c41.58,1.6) 41.58,0

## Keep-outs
Keep-Out Layer:
  rectangle: 40.3,11.43 43.18,15.384
  rectangle: 40.3,7.476 43.18,11.43

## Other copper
TOP:
  rectangle net NetC30_2: 19.681,10.024 21.178,10.67
  rectangle net VIN: 7.665,6.19 8.771,7.181
  pour cut-out: 6.4,16.84 6.4,15.34 4.9,15.34 4.9,14.04 3.1,14.04 3.1,8.561 4.726,8.561 4.726,7.54 6.3,7.54 6.3,6.102 0,6.102 0,16.82
  region net NetR44_1: 19.989,7.28 19.989,7.98 19.885,7.98 19.789,7.884 19.789,7.28
  region net NetR39_1: 10.784,15.225 10.647,15.362 10.647,15.958 cw(c10.714,15.958) 10.714,16.025 11.281,16.025 cw(c11.281,15.958) 11.347,15.958 11.347,15.291 cw(c11.281,15.291) 11.281,15.225
  region: 14.152,6.547 14.152,6.297 13.552,6.297 13.352,6.497 13.352,6.547
  region net NetR15_1: 11.552,6.547 11.552,6.297 12.152,6.297 12.352,6.497 12.352,6.547
  region net NetC51_2: 12.477,5.297 12.227,5.297 12.227,5.925 12.399,6.097 12.477,6.097
  region net NetC39_1: 13.227,5.297 13.477,5.297 13.477,5.925 13.305,6.097 13.227,6.097
L2_GND:
  pour cut-out: 6.4,16.84 6.4,15.34 4.9,15.34 4.9,14.04 3.218,14.04 3.218,8.561 4.9,8.561 4.9,7.692 6.3,7.692 6.3,6.016 0,6.016 0,16.84
L3_SIG:
  pour cut-out: 6.4,16.84 6.4,15.34 4.9,15.34 4.9,14.04 3.1,14.04 3.1,8.561 4.726,8.561 4.726,7.54 6.3,7.54 6.3,6.102 0,6.102 0,16.82
L4_PWR:
  pour cut-out: 6.4,16.84 6.4,15.34 4.9,15.34 4.9,14.04 3.1,14.04 3.1,8.561 4.726,8.561 4.726,7.54 6.3,7.54 6.3,6.102 0,6.102 0,16.82
L5_GND:
  pour cut-out: 6.4,16.84 6.4,15.34 4.9,15.34 4.9,14.04 3.1,14.04 3.1,8.561 4.726,8.561 4.726,7.54 6.3,7.54 6.3,6.102 0,6.102 0,16.82
BOTTOM:
  pour cut-out: 6.4,16.84 6.4,15.34 4.9,15.34 4.9,14.04 3.1,14.04 3.1,8.561 4.726,8.561 4.726,7.54 6.3,7.54 6.3,6.102 0,6.102 0,16.82

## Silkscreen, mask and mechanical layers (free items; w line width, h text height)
Top Designator:
  drawing of 1125 lines, arcs and shapes, not listed
Route Tool Path:
  lines w2: -1,7.097 -1,15.76 ; 44.18,8.29 44.18,1.597 ; 44.18,13.79 44.18,21.26 ; -1,1.597 ccw(c1.6,1.6) 1.6,-1 ; -1,1.597 cw(c1.6,1.6) -1,1.6 ccw(c0,1.6) -1,1.597 ; -1,21.26 cw(c1.6,21.26) 1.597,23.86 ; -1,21.26 -1,21.26 ; 1.597,23.86 cw(c1.6,22.86) 1.6,23.86 ; 1.597,23.86 cw(c1.6,21.26) 1.6,23.86 ; 1.6,-1 41.58,-1 ; 1.6,-1 1.6,-1 ; 1.6,23.86 41.58,23.86 ; 41.58,-1 ccw(c41.58,1.6) 44.18,1.597 ; 41.58,-1 41.58,-1 ; 41.58,23.86 cw(c41.58,21.26) 41.583,23.86 ; 41.58,23.86 cw(c41.58,22.86) 41.583,23.86 ; 41.583,23.86 cw(c41.58,21.26) 44.18,21.263 ; 44.18,1.597 ccw(c43.18,1.6) 44.18,1.6 cw(c41.58,1.6) 44.18,1.597 ; 44.18,21.26 ccw(c41.58,21.26) 44.18,21.263 ; 44.18,21.26 ccw(c43.18,21.26) 44.18,21.263
Board:
  lines w0.05: 0,1.6 ccw(c1.6,1.6) 1.6,0 ; 0,1.6 ccw(c1.6,1.6) 1.6,0 ; 0,1.6 0,21.26 ; 0,1.6 0,21.26 ; 0,21.26 cw(c1.6,21.26) 1.6,22.86 ; 0,21.26 cw(c1.6,21.26) 1.6,22.86 ; 1.6,0 41.58,0 ; 1.6,0 41.58,0 ; 1.6,22.86 41.58,22.86 ; 1.6,22.86 41.58,22.86 ; 41.58,0 ccw(c41.58,1.6) 43.18,1.6 ; 41.58,0 ccw(c41.58,1.6) 43.18,1.6 ; 41.58,22.86 cw(c41.58,21.26) 43.18,21.26 ; 41.58,22.86 cw(c41.58,21.26) 43.18,21.26 ; 43.18,1.6 43.18,21.26 ; 43.18,1.6 43.18,21.26
Mechanical 7:
  lines w0.1: 1.193,14.351 1.778,14.351 ; 1.193,16.891 1.778,16.891 ; 1.778,13.766 1.778,14.351 ; 1.778,14.936 1.778,14.351 ; 1.778,16.306 1.778,16.891 ; 1.778,17.476 1.778,16.891 ; 2.363,14.351 1.778,14.351 ; 2.363,16.891 1.778,16.891
AZUKI_TESTPOINTS:
  drawing of 156 lines, arcs and shapes, not listed
Nano_MECHANICAL_QUOTES_TP:
  drawing of 309 lines, arcs and shapes, not listed
  text "D12" at 3.435,17.68 h0.3
  text "D11" at 6.025,17.68 h0.3
  text "D10" at 8.515,17.68 h0.3
  text "D9" at 11.18,17.68 h0.3
  text "D9" at 11.18,17.68 h0.3
  text "D8" at 13.72,17.68 h0.3
  text "D7" at 16.26,17.68 h0.3
  text "D6" at 18.8,17.68 h0.3
  text "D5" at 21.325,17.68 h0.3
  text "D4" at 23.865,17.68 h0.3
  text "D3" at 26.42,17.68 h0.3
  text "D2" at 28.96,17.68 h0.3
  text "GND" at 31.35,17.68 h0.3
  text "NRST" at 33.74,17.68 h0.3
  text "D1" at 36.63,17.68 h0.3
  text "D0" at 39.12,17.68 h0.3
  text "RX" at 36.58,17.08 h0.3
  text "TX" at 39.12,17.08 h0.3
  text "USB DN" at 2.5,16.65 h0.3
  text "USB DP" at 2.5,13.801 h0.3
  text "GND" at 37.663,13.811 h0.3
  text "D13" at 40.228,13.811 h0.3
  text "D13" at 37.688,11.271 h0.3
  text "D13" at 40.228,11.271 h0.3
  text "D13" at 37.688,8.731 h0.3
  text "D13" at 40.228,8.731 h0.3
  text "VUSB" at 31.245,8.331 h0.3
  text "D13" at 3.435,5.56 h0.3
  text "VREF OR" at 7.89,5.56 h0.3
  text "VBUS" at 31.2,5.56 h0.3
  text "NRST OR" at 33.29,5.56 h0.3
  text "SCK" at 3.41,4.96 h0.3
  text "OTHER" at 8.19,4.96 h0.3
  text "5V" at 31.5,4.96 h0.3
  text "OTHER" at 33.59,4.96 h0.3
  text "3V3" at 5.95,4.86 h0.3
  text "A0" at 11.18,4.86 h0.3
  text "A0" at 11.18,4.86 h0.3
  text "A1" at 13.77,4.86 h0.3
  text "A2" at 16.26,4.86 h0.3
  text "A3" at 18.8,4.86 h0.3
  text "A6" at 26.42,4.86 h0.3
  text "A7" at 28.96,4.86 h0.3
  text "GND" at 36.43,4.86 h0.3
  text "VIN" at 38.995,4.86 h0.3
  text "A4" at 21.325,4.851 h0.3
  text "A5" at 23.865,4.851 h0.3

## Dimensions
0,2.54 to 1.778,14.351 on Mechanical 16
0,2.54 to 3.81,3.81 on Mechanical 16
0,2.54 to 1.27,3.81 on Mechanical 16
0,2.54 to 1.27,19.05 on Mechanical 16
0,2.54 to 1.81,17.2 on Mechanical 16
0,2.54 to 1.778,14.351 on Mechanical 16
0,2.54 to 1.27,3.81 on Mechanical 16
0,2.54 to 0,20.32 on Mechanical 16
0,2.54 to 43.18,2.54 on Mechanical 16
